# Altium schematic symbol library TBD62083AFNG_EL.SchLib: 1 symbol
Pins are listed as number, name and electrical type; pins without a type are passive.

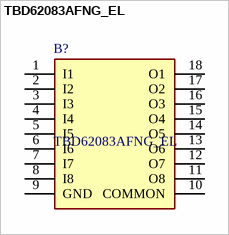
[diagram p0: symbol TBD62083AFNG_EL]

## TBD62083AFNG_EL
designator B?
BiCD Integrated Circuit Silicon Monolithic; Manufacturer_Name: Toshiba; Manufacturer_Part_Number: TBD62083AFNG,EL; Geometry.Height: 2.45mm
footprint SOIC127P1030X245-18N
pins: 1 I1, 2 I2, 3 I3, 4 I4, 5 I5, 6 I6, 7 I7, 8 I8, 9 GND, 10 COMMON, 11 O8, 12 O7, 13 O6, 14 O5, 15 O4, 16 O3, 17 O2, 18 O1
